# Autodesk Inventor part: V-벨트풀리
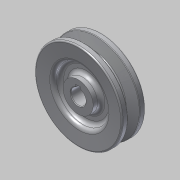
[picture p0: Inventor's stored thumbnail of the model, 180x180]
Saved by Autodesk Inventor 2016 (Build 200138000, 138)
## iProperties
Created: 2016-08
Part Number: V-벨트풀리
Material: 알루미늄 6061
Document SubType Name: Modeling
Designer: mduedu
Density: 2.71 g/cm^3
Appearance: 알루미늄 - 평지
Author: mduedu
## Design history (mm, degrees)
sketch "스케치1"
  geometry: L1 (0, 9.5)-(0, -9.5); L2 (0, 9.5)-(35, 9.5); L3 (35, 9.5)-(35, 4.825); L4 (35, 4.825)-(26, 2.074); L5 (26, 2.074)-(26, 0); L6 (0, 0)-(26, 0); L7 (0, -9.5)-(35, -9.5); L8 (35, -9.5)-(35, -4.825); L9 (35, -4.825)-(26, -2.074); L10 (26, -2.074)-(26, 0); L11 (32.3, 9.5)-(32.3, -9.5); 3 further points
  constraints: 22 end point, 6 point on line, 4 perpendicular, 3 symmetric about line, 1 coincident, 1 horizontal alignment, 1 midpoint, 1 parallel, 1 vertical
  dimensions: "d0" = 19 distance of L1.start L1.end; "d2" = 70 diameter of L8 L1; "d4" = 6.3 distance between parallel lines of L10 L11; "d5" = 2.7 distance between parallel lines of L11 L8; "d6" = 8 distance of point (32.3, -4) point (32.3, 4); "d7" = 34 deg angle of L9 L4
revolve "회전1" sketch "스케치1" stored, may be unused: angle "d8" = 90 deg
sketch "스케치2"
  geometry: L1 (-2, 0)-(2, 0); L2 (2, 0)-(2, 7.8); L3 (2, 7.8)-(-2, 7.8); L4 (-2, 7.8)-(-2, 0); C1 r 6 at (0, 0); 2 further points
  constraints: 8 end point, 2 coincident, 2 parallel, 1 centre point, 1 horizontal, 1 midpoint, 1 perpendicular
  dimensions: "d9" = 12 diameter of C1; "d11" = 4 distance of L2.end L3.end; "d12" = 7.8 distance of L1.end L2.end
extrude "돌출1" cut sketch "스케치2" stored distance "d13" = 10; taper "d14" = 0 deg
sketch "스케치3"
  geometry: L1 (35, 4.825)-(26, 2.074) reference; L2 (26, 2.074)-(26, -2.074) reference; L3 (0, 0)-(26, 0); L4 (35, 9.5)-(35, 4.825) reference; L5 (-35, 9.5)-(35, 9.5) reference; L6 (35, 9.5)-(21, 8.275); L7 (21, 8.275)-(21, 3); L8 (21, 3)-(12, 3); L9 (12, 3)-(12, 9.5); L10 (0, 9.5)-(0, -9.5); L11 (5.657, -9.5)-(-6, -9.5) reference; L12 (12, 9.5)-(35, 9.5)
  constraints: 14 end point, 3 midpoint, 2 perpendicular, 2 point on line, 1 collinear, 1 horizontal, 1 parallel
  dimensions: "d15" = 3 distance between parallel lines of L3 L8; "d17" = 42 diameter of L7 L10; "d18" = 24 diameter of L9 L10; "d31" = 5 deg angle of L6 L5
revolve "회전2" sketch "스케치3" stored, may be unused: angle "d19" = 90 deg
fillet "모깎기1" dims "d20" = 0.5, "d21" = 1, "d22" = 1
fillet "모깎기2" dims "d23" = 3
fillet "모깎기3" dims "d24" = 3
fillet "모깎기4" dims "d25" = 3
chamfer "모따기1" distance "d26" = 0.5; stored, may be unused: second distance "d27" = 2, angle "d28" = 45 deg
node "솔리드1"
mirror "대칭1"
